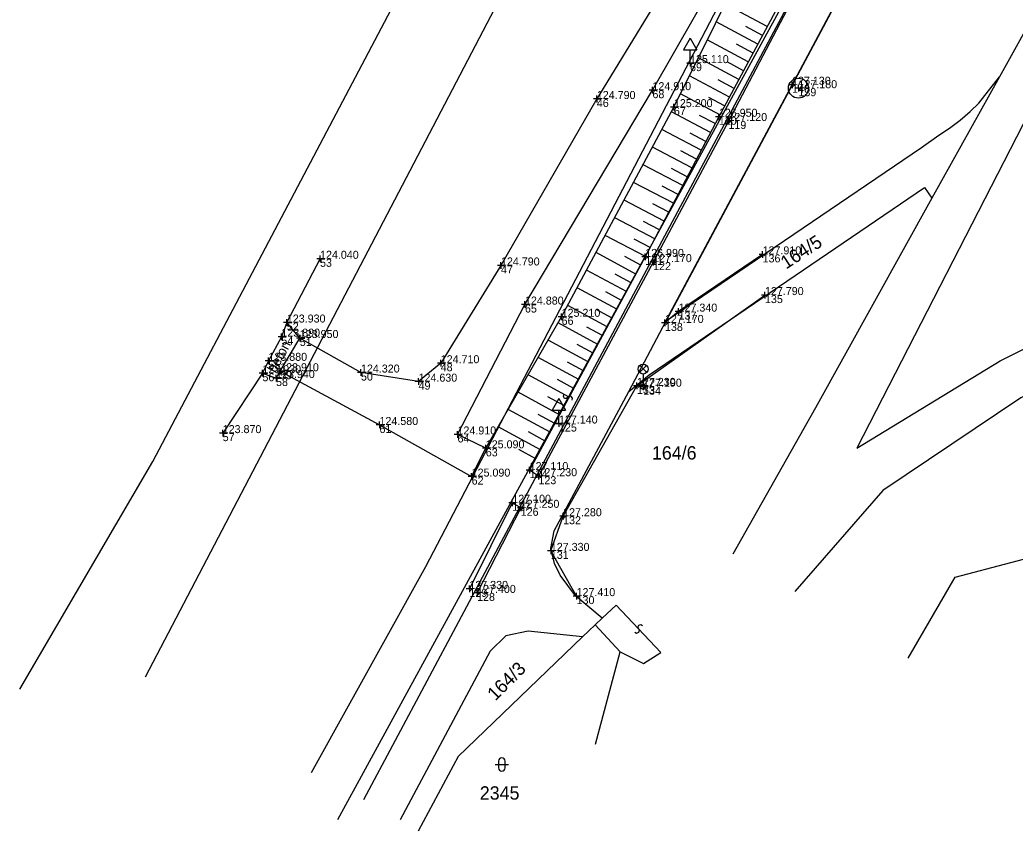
# Model space of a CAD drawing. Extents: x -747268 to -747054, y -964730 to -964532.
# Drawn here: x -747267.8 to -747193.2, y -964730 to -964669.2 of the extents above; entities that cross this region are included whole.
import ezdxf

# ---------------------------------------------------------------- set-up
doc = ezdxf.new("R2010")
doc.units = 0
for name, color, linetype in [('Body polohopisu', 7, 'Continuous'), ('Doplňkové značky', 7, 'Continuous'), ('KM', 7, 'Continuous'), ('Ploty_opěrné zdi', 7, 'Continuous'), ('Popisy objektů_povrchů', 7, 'Continuous'), ('Rozhraní ploch', 7, 'Continuous'), ('Vnitřní kresba', 7, 'Continuous'), ('Výškopis', 7, 'Continuous'), ('Výšky bodů', 7, 'Continuous'), ('Čísla bodů', 7, 'Continuous')]:
    doc.layers.add(name, color=color, linetype=linetype)

msp = doc.modelspace()

# ---------------------------------------------------------------- linework, layer by layer
at = {"layer": 'Body polohopisu'}
for p, q in [((-747217.58, -964672.39), (-747217.58, -964672.14)), ((-747217.58, -964672.39), (-747217.83, -964672.39)), ((-747217.58, -964672.39), (-747217.33, -964672.39)), ((-747217.58, -964672.39), (-747217.58, -964672.64)), ((-747209.93, -964674.01), (-747209.93, -964673.76)), ((-747220.4, -964674.42), (-747220.65, -964674.42)), ((-747220.4, -964674.42), (-747220.4, -964674.17)), ((-747220.4, -964674.42), (-747220.15, -964674.42)), ((-747220.4, -964674.42), (-747220.4, -964674.67)), ((-747209.93, -964674.01), (-747210.18, -964674.01)), ((-747209.93, -964674.01), (-747209.68, -964674.01)), ((-747209.93, -964674.01), (-747209.93, -964674.26)), ((-747209.45, -964674.27), (-747209.7, -964674.27)), ((-747209.45, -964674.27), (-747209.45, -964674.02)), ((-747209.45, -964674.27), (-747209.2, -964674.27)), ((-747209.45, -964674.27), (-747209.45, -964674.52)), ((-747224.57, -964675.08), (-747224.82, -964675.08)), ((-747224.57, -964675.08), (-747224.57, -964674.83)), ((-747224.57, -964675.08), (-747224.32, -964675.08)), ((-747224.57, -964675.08), (-747224.57, -964675.33)), ((-747218.79, -964675.69), (-747219.04, -964675.69)), ((-747218.79, -964675.69), (-747218.79, -964675.44)), ((-747218.79, -964675.69), (-747218.54, -964675.69)), ((-747218.79, -964675.69), (-747218.79, -964675.94)), ((-747215.42, -964676.41), (-747215.67, -964676.41)), ((-747215.42, -964676.41), (-747215.42, -964676.16)), ((-747215.42, -964676.41), (-747215.17, -964676.41)), ((-747215.42, -964676.41), (-747215.42, -964676.66)), ((-747214.7, -964676.73), (-747214.95, -964676.73)), ((-747214.7, -964676.73), (-747214.7, -964676.48)), ((-747214.7, -964676.73), (-747214.45, -964676.73)), ((-747214.7, -964676.73), (-747214.7, -964676.98)), ((-747212.14, -964686.73), (-747212.14, -964686.48)), ((-747245.33, -964687.06), (-747245.58, -964687.06)), ((-747245.33, -964687.06), (-747245.33, -964686.81)), ((-747245.33, -964687.06), (-747245.08, -964687.06)), ((-747245.33, -964687.06), (-747245.33, -964687.31)), ((-747220.94, -964686.92), (-747221.19, -964686.92)), ((-747220.94, -964686.92), (-747220.94, -964686.67)), ((-747220.94, -964686.92), (-747220.69, -964686.92)), ((-747220.94, -964686.92), (-747220.94, -964687.17)), ((-747220.35, -964687.31), (-747220.35, -964687.06)), ((-747212.14, -964686.73), (-747212.39, -964686.73)), ((-747212.14, -964686.73), (-747211.89, -964686.73)), ((-747212.14, -964686.73), (-747212.14, -964686.98)), ((-747231.76, -964687.56), (-747232.01, -964687.56)), ((-747231.76, -964687.56), (-747231.76, -964687.31)), ((-747231.76, -964687.56), (-747231.51, -964687.56)), ((-747231.76, -964687.56), (-747231.76, -964687.81)), ((-747220.35, -964687.31), (-747220.6, -964687.31)), ((-747220.35, -964687.31), (-747220.1, -964687.31)), ((-747220.35, -964687.31), (-747220.35, -964687.56)), ((-747211.96, -964689.78), (-747212.21, -964689.78)), ((-747211.96, -964689.78), (-747211.96, -964689.53)), ((-747211.96, -964689.78), (-747211.71, -964689.78)), ((-747211.96, -964689.78), (-747211.96, -964690.03)), ((-747229.96, -964690.49), (-747230.21, -964690.49)), ((-747229.96, -964690.49), (-747229.96, -964690.24)), ((-747229.96, -964690.49), (-747229.71, -964690.49)), ((-747229.96, -964690.49), (-747229.96, -964690.74)), ((-747218.44, -964691.02), (-747218.44, -964690.77)), ((-747247.82, -964691.84), (-747247.82, -964691.59)), ((-747227.21, -964691.41), (-747227.46, -964691.41)), ((-747227.21, -964691.41), (-747227.21, -964691.16)), ((-747227.21, -964691.41), (-747226.96, -964691.41)), ((-747227.21, -964691.41), (-747227.21, -964691.66)), ((-747219.46, -964691.87), (-747219.46, -964691.62)), ((-747218.44, -964691.02), (-747218.69, -964691.02)), ((-747218.44, -964691.02), (-747218.19, -964691.02)), ((-747218.44, -964691.02), (-747218.44, -964691.27)), ((-747247.82, -964691.84), (-747248.07, -964691.84)), ((-747247.82, -964691.84), (-747247.57, -964691.84)), ((-747247.82, -964691.84), (-747247.82, -964692.09)), ((-747219.46, -964691.87), (-747219.71, -964691.87)), ((-747219.46, -964691.87), (-747219.21, -964691.87)), ((-747219.46, -964691.87), (-747219.46, -964692.12)), ((-747248.23, -964692.9), (-747248.48, -964692.9)), ((-747248.23, -964692.9), (-747248.23, -964692.65)), ((-747248.23, -964692.9), (-747247.98, -964692.9)), ((-747248.23, -964692.9), (-747248.23, -964693.15)), ((-747246.85, -964693), (-747247.1, -964693)), ((-747246.85, -964693), (-747246.85, -964692.75)), ((-747246.85, -964693), (-747246.6, -964693)), ((-747246.85, -964693), (-747246.85, -964693.25)), ((-747249.2, -964694.71), (-747249.2, -964694.46)), ((-747236.28, -964694.89), (-747236.28, -964694.64)), ((-747249.65, -964695.64), (-747249.65, -964695.39)), ((-747249.2, -964694.71), (-747249.45, -964694.71)), ((-747249.2, -964694.71), (-747248.95, -964694.71)), ((-747249.2, -964694.71), (-747249.2, -964694.96)), ((-747248.32, -964695.49), (-747248.32, -964695.24)), ((-747242.26, -964695.59), (-747242.26, -964695.34)), ((-747236.28, -964694.89), (-747236.53, -964694.89)), ((-747236.28, -964694.89), (-747236.03, -964694.89)), ((-747236.28, -964694.89), (-747236.28, -964695.14)), ((-747249.65, -964695.64), (-747249.9, -964695.64)), ((-747249.65, -964695.64), (-747249.4, -964695.64)), ((-747249.65, -964695.64), (-747249.65, -964695.89)), ((-747248.63, -964696), (-747248.88, -964696)), ((-747248.63, -964696), (-747248.63, -964695.75)), ((-747248.63, -964696), (-747248.38, -964696)), ((-747248.63, -964696), (-747248.63, -964696.25)), ((-747248.32, -964695.49), (-747248.57, -964695.49)), ((-747248.32, -964695.49), (-747248.07, -964695.49)), ((-747248.32, -964695.49), (-747248.32, -964695.74)), ((-747242.26, -964695.59), (-747242.51, -964695.59)), ((-747242.26, -964695.59), (-747242.01, -964695.59)), ((-747242.26, -964695.59), (-747242.26, -964695.84)), ((-747237.94, -964696.27), (-747237.94, -964696.02)), ((-747237.94, -964696.27), (-747238.19, -964696.27)), ((-747237.94, -964696.27), (-747237.69, -964696.27)), ((-747237.94, -964696.27), (-747237.94, -964696.52)), ((-747221.56, -964696.59), (-747221.81, -964696.59)), ((-747221.56, -964696.59), (-747221.56, -964696.34)), ((-747221.56, -964696.59), (-747221.31, -964696.59)), ((-747221.56, -964696.59), (-747221.56, -964696.84)), ((-747221.1, -964696.65), (-747221.35, -964696.65)), ((-747221.1, -964696.65), (-747221.1, -964696.4)), ((-747221.1, -964696.65), (-747220.85, -964696.65)), ((-747221.1, -964696.65), (-747221.1, -964696.9)), ((-747227.41, -964699.41), (-747227.41, -964699.16)), ((-747252.63, -964700.13), (-747252.63, -964699.88)), ((-747240.87, -964699.52), (-747241.12, -964699.52)), ((-747240.87, -964699.52), (-747240.87, -964699.27)), ((-747240.87, -964699.52), (-747240.62, -964699.52)), ((-747240.87, -964699.52), (-747240.87, -964699.77)), ((-747227.41, -964699.41), (-747227.66, -964699.41)), ((-747227.41, -964699.41), (-747227.16, -964699.41)), ((-747227.41, -964699.41), (-747227.41, -964699.66)), ((-747252.63, -964700.13), (-747252.88, -964700.13)), ((-747252.63, -964700.13), (-747252.38, -964700.13)), ((-747252.63, -964700.13), (-747252.63, -964700.38)), ((-747235.02, -964700.23), (-747235.27, -964700.23)), ((-747235.02, -964700.23), (-747235.02, -964699.98)), ((-747235.02, -964700.23), (-747234.77, -964700.23)), ((-747235.02, -964700.23), (-747235.02, -964700.48)), ((-747232.9, -964701.27), (-747233.15, -964701.27)), ((-747232.9, -964701.27), (-747232.9, -964701.02)), ((-747232.9, -964701.27), (-747232.65, -964701.27)), ((-747232.9, -964701.27), (-747232.9, -964701.52)), ((-747229.61, -964702.9), (-747229.86, -964702.9)), ((-747229.61, -964702.9), (-747229.61, -964702.65)), ((-747229.61, -964702.9), (-747229.36, -964702.9)), ((-747229.61, -964702.9), (-747229.61, -964703.15)), ((-747233.96, -964703.39), (-747234.21, -964703.39)), ((-747233.96, -964703.39), (-747233.96, -964703.14)), ((-747233.96, -964703.39), (-747233.71, -964703.39)), ((-747233.96, -964703.39), (-747233.96, -964703.64)), ((-747228.95, -964703.36), (-747229.2, -964703.36)), ((-747228.95, -964703.36), (-747228.95, -964703.11)), ((-747228.95, -964703.36), (-747228.7, -964703.36)), ((-747228.95, -964703.36), (-747228.95, -964703.61)), ((-747230.91, -964705.35), (-747230.91, -964705.1)), ((-747230.91, -964705.35), (-747231.16, -964705.35)), ((-747230.91, -964705.35), (-747230.66, -964705.35)), ((-747230.91, -964705.35), (-747230.91, -964705.6)), ((-747230.28, -964705.73), (-747230.53, -964705.73)), ((-747230.28, -964705.73), (-747230.28, -964705.48)), ((-747230.28, -964705.73), (-747230.03, -964705.73)), ((-747230.28, -964705.73), (-747230.28, -964705.98)), ((-747227.1, -964706.36), (-747227.35, -964706.36)), ((-747227.1, -964706.36), (-747227.1, -964706.11)), ((-747227.1, -964706.36), (-747226.85, -964706.36)), ((-747227.1, -964706.36), (-747227.1, -964706.61)), ((-747228.02, -964708.96), (-747228.02, -964708.71)), ((-747228.02, -964708.96), (-747228.27, -964708.96)), ((-747228.02, -964708.96), (-747227.77, -964708.96)), ((-747228.02, -964708.96), (-747228.02, -964709.21)), ((-747234.13, -964711.81), (-747234.38, -964711.81)), ((-747234.13, -964711.81), (-747234.13, -964711.56)), ((-747234.13, -964711.81), (-747233.88, -964711.81)), ((-747234.13, -964711.81), (-747234.13, -964712.06)), ((-747233.55, -964712.11), (-747233.55, -964711.86)), ((-747233.55, -964712.11), (-747233.8, -964712.11)), ((-747233.55, -964712.11), (-747233.3, -964712.11)), ((-747233.55, -964712.11), (-747233.55, -964712.36)), ((-747226.09, -964712.35), (-747226.34, -964712.35)), ((-747226.09, -964712.35), (-747226.09, -964712.1)), ((-747226.09, -964712.35), (-747225.84, -964712.35)), ((-747226.09, -964712.35), (-747226.09, -964712.6))]:
    msp.add_line(p, q, dxfattribs=at)
at = {"layer": 'Doplňkové značky'}
for p, q in [((-747217.58, -964670.524), (-747218.08, -964671.39)), ((-747217.58, -964670.524), (-747217.08, -964671.39)), ((-747218.08, -964671.39), (-747217.08, -964671.39)), ((-747217.58, -964672.39), (-747217.58, -964671.39)), ((-747217.83, -964672.39), (-747217.33, -964672.39)), ((-747221.364, -964695.588), (-747220.836, -964695.06)), ((-747220.828, -964695.585), (-747221.356, -964695.056)), ((-747221.1, -964695.7), (-747221.1, -964696.45)), ((-747227.41, -964697.544), (-747227.91, -964698.41)), ((-747227.41, -964697.544), (-747226.91, -964698.41)), ((-747227.91, -964698.41), (-747226.91, -964698.41)), ((-747227.41, -964699.41), (-747227.41, -964698.41)), ((-747227.66, -964699.41), (-747227.16, -964699.41))]:
    msp.add_line(p, q, dxfattribs=at)
for centre, radius in [((-747209.45, -964674.27), 0.75), ((-747221.1, -964695.325), 0.375), ((-747221.1, -964696.65), 0.2)]:
    msp.add_circle(centre, radius, dxfattribs=at)
at = {"layer": 'KM'}
for p, q in [((-747194.37, -964673.41), (-747199.44, -964682.52)), ((-747222.18, -964697), (-747219.36, -964691.72)), ((-747224.7, -964714.51), (-747225.64, -964715.41)), ((-747232.203, -964724.981), (-747231.201, -964724.981)), ((-747231.953, -964724.731), (-747231.953, -964725.231)), ((-747231.451, -964725.231), (-747231.451, -964724.731))]:
    msp.add_line(p, q, dxfattribs=at)
for points in [[(-747258.428, -964718.402), (-747225.89, -964656.18), (-747178.58, -964571.79), (-747161.768, -964542.826)], [(-747245.973, -964725.574), (-747237.39, -964710.13), (-747213.15, -964663.66), (-747212.04, -964661.58), (-747205.52, -964649.38), (-747207.93, -964646.01), (-747172.64, -964585.56), (-747171.18, -964583.16), (-747172.38, -964582.51), (-747172.75, -964582.31), (-747169.52, -964576.73), (-747168.08, -964577.53), (-747165.21, -964574.13), (-747160.86, -964564.14), (-747155.16, -964551.47), (-747155.48, -964551.37), (-747155.09, -964550.12), (-747154.28, -964550.33), (-747154.06, -964549.5), (-747153.365, -964547.044)], [(-747242.047, -964727.609), (-747230.16, -964705.36), (-747208.97, -964665.66), (-747208.88, -964665.32), (-747209.05, -964664.92), (-747208.39, -964663.57), (-747207.91, -964663.49), (-747207.6, -964663.09), (-747199.41, -964647.48), (-747199.14, -964646.95), (-747194.94, -964639.04), (-747194.8, -964638.66), (-747194.08, -964638.4), (-747193.89, -964638.17), (-747178.12, -964607.48), (-747165.52, -964582.92), (-747162.81, -964577.62), (-747161.38, -964574.2), (-747160.49, -964571.42), (-747153.77, -964550.39), (-747154.12, -964550.42), (-747153.81, -964549.44), (-747153.109, -964547.254)], [(-747149.729, -964549.086), (-747149.93, -964549.71), (-747150.35, -964549.8), (-747157.75, -964573.23), (-747158.53, -964575.6), (-747159.7, -964578.37), (-747163.23, -964585.33), (-747175.42, -964609.03), (-747186.84, -964631.22), (-747187.01, -964633.47), (-747185.08, -964635.94), (-747196.29, -964656.98), (-747198.54, -964658.68), (-747199.84, -964658.63), (-747201.84, -964659.38), (-747202.78, -964660.64), (-747203.73, -964662.42), (-747219.36, -964691.72)], [(-747179.78, -964638.67), (-747191.19, -964659.92), (-747188.06, -964662.04), (-747194.37, -964673.41)], [(-747170.03, -964639.52), (-747191.65, -964675.11), (-747205.07, -964701.27), (-747194.33, -964694.71), (-747168.43, -964681.69), (-747141.95, -964674.74), (-747119.57, -964669.71), (-747114.21, -964668.06), (-747110.99, -964665.85), (-747107.13, -964660.6)], [(-747104.3, -964675.97), (-747110.73, -964672.35), (-747113.2, -964673.81), (-747141.15, -964677.79), (-747165.83, -964684.28), (-747192.76, -964697.48), (-747203.13, -964704.43), (-747209.73, -964711.996)], [(-747219.36, -964691.72), (-747200.23, -964678.71), (-747198.91, -964677.79), (-747198.11, -964677.27), (-747197.31, -964676.67), (-747196.56, -964676.02), (-747195.92, -964675.4), (-747194.37, -964673.41)], [(-747222.18, -964697), (-747220.64, -964695.77), (-747200, -964681.71), (-747199.44, -964682.52)], [(-747199.44, -964682.52), (-747208.18, -964698.23), (-747214.377, -964709.194)], [(-747224.7, -964714.51), (-747224.16, -964714), (-747226.16, -964712.32), (-747227.33, -964710.79), (-747227.75, -964709.91), (-747228.03, -964708.77), (-747227.76, -964707.45), (-747222.18, -964697)], [(-747201.228, -964716.992), (-747197.7, -964710.92), (-747185.17, -964707.62), (-747166.03, -964703.32), (-747141.08, -964710.85), (-747134.49, -964709.31), (-747125.59, -964712.6), (-747114.89, -964709.21), (-747113.01, -964712.26), (-747107.669, -964711.374)], [(-747224.665, -964723.454), (-747222.81, -964716.53), (-747224.7, -964714.51)], [(-747225.64, -964715.41), (-747229.73, -964714.98), (-747231.4, -964715.34), (-747232.57, -964716.49), (-747239.31, -964729.132)], [(-747225.64, -964715.41), (-747234.96, -964724.38), (-747237.963, -964729.967)]]:
    msp.add_lwpolyline(points, dxfattribs=at)
for centre, start, end in [((-747231.702, -964724.73), 0, 180), ((-747231.702, -964725.23), 180, 359.98789)]:
    msp.add_arc(centre, 0.25, start, end, dxfattribs=at)
at = {"layer": 'Ploty_opěrné zdi'}
msp.add_lwpolyline([(-747212.14, -964686.73), (-747218.44, -964691.02)], dxfattribs=at)
at = {"layer": 'Rozhraní ploch'}
for points in [[(-747164.8, -964581.46), (-747168.98, -964589.75), (-747182.91, -964616.97), (-747186.63, -964624.1), (-747193.85, -964638.28), (-747194.38, -964638.56), (-747199.08, -964647.44), (-747204.82, -964658.33), (-747208.77, -964665.45), (-747214.7, -964676.73), (-747220.35, -964687.31), (-747228.95, -964703.36)], [(-747207.74, -964618.01), (-747209.42, -964620.7), (-747207.13, -964621.42), (-747205.64, -964619.2), (-747202.99, -964624.62), (-747199.45, -964632.07), (-747215.93, -964660.89), (-747224.57, -964675.08), (-747231.76, -964687.56), (-747236.28, -964694.89), (-747237.94, -964696.27), (-747242.26, -964695.59), (-747246.85, -964693), (-747247.82, -964691.84), (-747248.23, -964692.9)], [(-747212.14, -964686.73), (-747218.44, -964691.02), (-747219.46, -964691.87), (-747209.93, -964674.01), (-747202.82, -964660.7), (-747201.3, -964658.87), (-747199.71, -964658.58), (-747200.02, -964667.66)], [(-747232.9, -964701.27), (-747235.02, -964700.23), (-747229.96, -964690.49), (-747220.4, -964674.42), (-747214, -964663.21), (-747212.54, -964663.12)], [(-747226.09, -964712.35), (-747228.02, -964708.96), (-747227.1, -964706.36), (-747221.56, -964696.59), (-747211.96, -964689.78)], [(-747248.23, -964692.9), (-747249.2, -964694.71)], [(-747248.32, -964695.49), (-747246.85, -964693)], [(-747249.2, -964694.71), (-747249.65, -964695.64), (-747248.63, -964696), (-747248.32, -964695.49), (-747240.87, -964699.52), (-747233.96, -964703.39)], [(-747233.96, -964703.39), (-747232.9, -964701.27)], [(-747228.95, -964703.36), (-747229.61, -964702.9)], [(-747230.28, -964705.73), (-747233.55, -964712.11)], [(-747230.28, -964705.73), (-747230.91, -964705.35)]]:
    msp.add_lwpolyline(points, dxfattribs=at)
at = {"layer": 'Vnitřní kresba'}
for p, q in [((-747257.86, -964702.26), (-747231.87, -964652.97)), ((-747209.18, -964665.33), (-747244.025, -964729.117)), ((-747267.84, -964719.33), (-747257.86, -964702.26)), ((-747223.12, -964713.02), (-747224.16, -964714)), ((-747219.76, -964716.57), (-747223.12, -964713.02)), ((-747222.81, -964716.53), (-747221.08, -964717.4)), ((-747221.08, -964717.4), (-747219.76, -964716.57))]:
    msp.add_line(p, q, dxfattribs=at)
for points in [[(-747226.413, -964697.658), (-747226.385, -964697.502), (-747226.492, -964697.375), (-747226.644, -964697.372), (-747226.834, -964697.542), (-747226.985, -964697.527), (-747227.079, -964697.396), (-747227.047, -964697.254)], [(-747221.723, -964715.042), (-747221.583, -964715.116), (-747221.429, -964715.053), (-747221.379, -964714.91), (-747221.483, -964714.677), (-747221.422, -964714.537), (-747221.269, -964714.488), (-747221.143, -964714.562)]]:
    msp.add_lwpolyline(points, dxfattribs=at)
at = {"layer": 'Výškopis'}
for points in [[(-747232.9, -964701.27), (-747227.21, -964691.41), (-747218.79, -964675.69), (-747212.54, -964663.12)], [(-747209.31, -964665.03), (-747215.42, -964676.41), (-747220.94, -964686.92), (-747229.61, -964702.9)], [(-747211.793, -964669.655), (-747214.948, -964667.962)], [(-747212.503, -964670.977), (-747215.616, -964669.306)], [(-747212.148, -964670.316), (-747213.402, -964669.643)], [(-747213.213, -964672.299), (-747216.284, -964670.65)], [(-747212.858, -964671.638), (-747214.095, -964670.974)], [(-747213.922, -964673.62), (-747216.952, -964671.993)], [(-747213.567, -964672.959), (-747214.788, -964672.304)], [(-747214.632, -964674.942), (-747217.62, -964673.337)], [(-747214.277, -964674.281), (-747215.481, -964673.635)], [(-747215.341, -964676.263), (-747218.288, -964674.681)], [(-747214.986, -964675.603), (-747216.174, -964674.965)], [(-747216.04, -964677.591), (-747218.981, -964676.046)], [(-747215.691, -964676.927), (-747216.869, -964676.308)], [(-747216.738, -964678.919), (-747219.689, -964677.368)], [(-747216.389, -964678.255), (-747217.567, -964677.636)], [(-747217.435, -964680.247), (-747220.397, -964678.691)], [(-747217.086, -964679.583), (-747218.269, -964678.961)], [(-747218.132, -964681.574), (-747221.106, -964680.013)], [(-747217.784, -964680.911), (-747218.971, -964680.287)], [(-747218.83, -964682.902), (-747221.814, -964681.335)], [(-747218.481, -964682.238), (-747219.673, -964681.613)], [(-747219.527, -964684.23), (-747222.522, -964682.658)], [(-747219.179, -964683.566), (-747220.374, -964682.938)], [(-747220.225, -964685.558), (-747223.23, -964683.98)], [(-747219.876, -964684.894), (-747221.076, -964684.264)], [(-747220.922, -964686.886), (-747223.939, -964685.302)], [(-747220.574, -964686.222), (-747221.778, -964685.59)], [(-747247.82, -964691.84), (-747245.33, -964687.06)], [(-747221.637, -964688.205), (-747224.625, -964686.584)], [(-747221.28, -964687.546), (-747222.476, -964686.897)], [(-747222.353, -964689.524), (-747225.333, -964687.906)], [(-747221.995, -964688.864), (-747223.189, -964688.217)], [(-747223.068, -964690.842), (-747226.042, -964689.229)], [(-747222.71, -964690.183), (-747223.901, -964689.537)], [(-747223.783, -964692.16), (-747226.75, -964690.551)], [(-747223.426, -964691.501), (-747224.614, -964690.857)], [(-747224.499, -964693.479), (-747227.473, -964691.865)], [(-747224.141, -964692.82), (-747225.326, -964692.177)], [(-747225.214, -964694.797), (-747228.223, -964693.165)], [(-747224.856, -964694.138), (-747226.053, -964693.489)], [(-747225.929, -964696.116), (-747228.973, -964694.465)], [(-747225.572, -964695.457), (-747226.782, -964694.8)], [(-747249.65, -964695.64), (-747252.63, -964700.13)], [(-747226.645, -964697.434), (-747229.723, -964695.764)], [(-747226.287, -964696.775), (-747227.511, -964696.111)], [(-747227.36, -964698.753), (-747230.473, -964697.064)], [(-747227.002, -964698.093), (-747228.24, -964697.422)], [(-747228.075, -964700.071), (-747231.223, -964698.363)], [(-747227.718, -964699.412), (-747228.97, -964698.733)], [(-747228.791, -964701.39), (-747231.973, -964699.663)], [(-747228.433, -964700.73), (-747229.699, -964700.044)], [(-747229.148, -964702.049), (-747230.428, -964701.354)], [(-747230.91, -964705.35), (-747234.13, -964711.81)]]:
    msp.add_lwpolyline(points, dxfattribs=at)

# ---------------------------------------------------------------- texts
at = {"layer": 'KM'}
for s, rotation, p in [('164/5', 33, (-747210.376, -964687.873)), ('164/3', 45, (-747232.186, -964720.252))]:
    msp.add_text(s, height=1, rotation=rotation, dxfattribs=at).set_placement(p)
for s, p in [('164/6', (-747220.438, -964702.11)), ('2345', (-747233.347, -964727.61))]:
    msp.add_text(s, height=1, dxfattribs=at).set_placement(p)
at = {"layer": 'Popisy objektů_povrchů'}
msp.add_text('beton', height=0.75, rotation=61.81263, dxfattribs=at).set_placement((-747248.671, -964695.668))
at = {"layer": 'Výšky bodů'}
for s, p in [('125.110', (-747217.58, -964672.39)), ('127.130', (-747209.93, -964674.01)), ('127.180', (-747209.45, -964674.27)), ('124.790', (-747224.57, -964675.08)), ('124.910', (-747220.4, -964674.42)), ('125.200', (-747218.79, -964675.69)), ('126.950', (-747215.42, -964676.41)), ('127.120', (-747214.7, -964676.73)), ('124.040', (-747245.33, -964687.06)), ('126.990', (-747220.94, -964686.92)), ('127.910', (-747212.14, -964686.73)), ('124.790', (-747231.76, -964687.56)), ('127.170', (-747220.35, -964687.31)), ('127.790', (-747211.96, -964689.78)), ('124.880', (-747229.96, -964690.49)), ('125.210', (-747227.21, -964691.41)), ('127.340', (-747218.44, -964691.02)), ('123.930', (-747247.82, -964691.84)), ('127.170', (-747219.46, -964691.87)), ('123.890', (-747248.23, -964692.9)), ('123.950', (-747246.85, -964693)), ('123.880', (-747249.2, -964694.71)), ('124.710', (-747236.28, -964694.89)), ('123.930', (-747249.65, -964695.64)), ('123.940', (-747248.63, -964696)), ('123.910', (-747248.32, -964695.49)), ('124.320', (-747242.26, -964695.59)), ('124.630', (-747237.94, -964696.27)), ('127.230', (-747221.56, -964696.59)), ('127.190', (-747221.1, -964696.65)), ('124.580', (-747240.87, -964699.52)), ('127.140', (-747227.41, -964699.41)), ('123.870', (-747252.63, -964700.13)), ('124.910', (-747235.02, -964700.23)), ('125.090', (-747232.9, -964701.27)), ('125.090', (-747233.96, -964703.39)), ('127.110', (-747229.61, -964702.9)), ('127.230', (-747228.95, -964703.36)), ('127.100', (-747230.91, -964705.35)), ('127.250', (-747230.28, -964705.73)), ('127.280', (-747227.1, -964706.36)), ('127.330', (-747228.02, -964708.96)), ('127.330', (-747234.13, -964711.81)), ('127.400', (-747233.55, -964712.11)), ('127.410', (-747226.09, -964712.35))]:
    msp.add_text(s, height=0.6, dxfattribs=at).set_placement(p)
at = {"layer": 'Čísla bodů'}
for s, p in [('69', (-747217.58, -964672.99)), ('68', (-747220.4, -964675.02)), ('140', (-747209.93, -964674.61)), ('139', (-747209.45, -964674.87)), ('46', (-747224.57, -964675.68)), ('67', (-747218.79, -964676.29)), ('120', (-747215.42, -964677.01)), ('119', (-747214.7, -964677.33)), ('53', (-747245.33, -964687.66)), ('121', (-747220.94, -964687.52)), ('136', (-747212.14, -964687.33)), ('47', (-747231.76, -964688.16)), ('122', (-747220.35, -964687.91)), ('135', (-747211.96, -964690.38)), ('65', (-747229.96, -964691.09)), ('66', (-747227.21, -964692.01)), ('137', (-747218.44, -964691.62)), ('52', (-747247.82, -964692.44)), ('138', (-747219.46, -964692.47)), ('54', (-747248.23, -964693.5)), ('51', (-747246.85, -964693.6)), ('55', (-747249.2, -964695.31)), ('48', (-747236.28, -964695.49)), ('56', (-747249.65, -964696.24)), ('58', (-747248.63, -964696.6)), ('59', (-747248.32, -964696.09)), ('50', (-747242.26, -964696.19)), ('49', (-747237.94, -964696.87)), ('133', (-747221.56, -964697.19)), ('134', (-747221.1, -964697.25)), ('61', (-747240.87, -964700.12)), ('125', (-747227.41, -964700.01)), ('57', (-747252.63, -964700.73)), ('64', (-747235.02, -964700.83)), ('63', (-747232.9, -964701.87)), ('124', (-747229.61, -964703.5)), ('62', (-747233.96, -964703.99)), ('123', (-747228.95, -964703.96)), ('127', (-747230.91, -964705.95)), ('126', (-747230.28, -964706.33)), ('132', (-747227.1, -964706.96)), ('131', (-747228.02, -964709.56)), ('129', (-747234.13, -964712.41)), ('128', (-747233.55, -964712.71)), ('130', (-747226.09, -964712.95))]:
    msp.add_text(s, height=0.6, dxfattribs=at).set_placement(p)

doc.saveas('drawing.dxf')
